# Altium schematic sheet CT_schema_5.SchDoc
size 368 x 245 mm
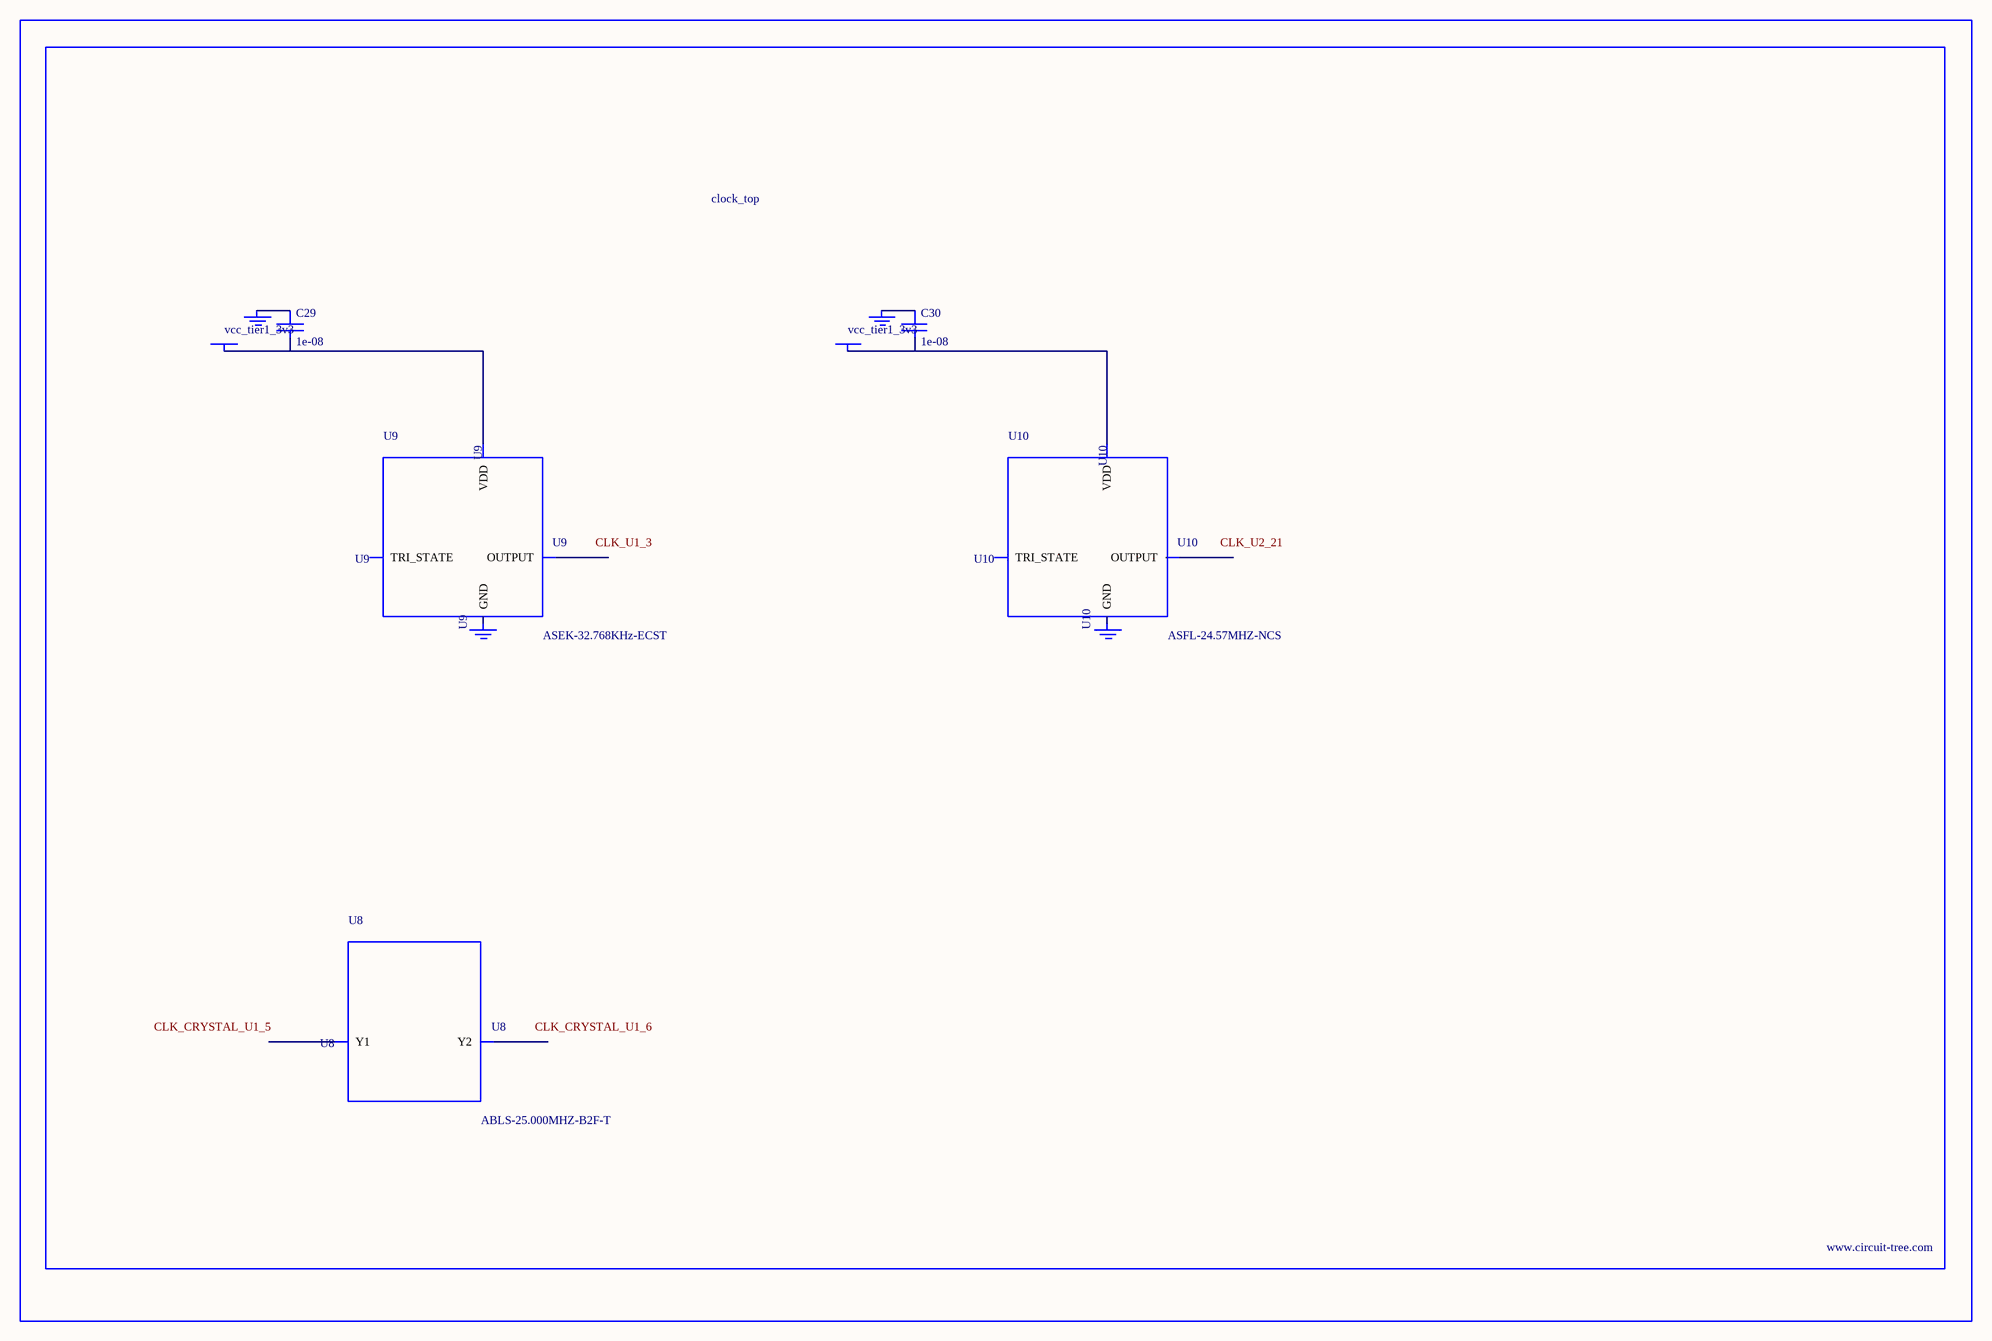
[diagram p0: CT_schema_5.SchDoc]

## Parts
BORDER4  (no value)
C29  1e-08  [C0402]
C30  1e-08  [C0402]
GND_INSTANCE_4_0  (no value)
GND_INSTANCE_4_1  (no value)
GND_INSTANCE_4_2  (no value)
GND_INSTANCE_4_3  (no value)
POWER_INSTANCE_4_0  vcc_tier1_3v3
POWER_INSTANCE_4_1  vcc_tier1_3v3
U8  ABLS-25.000MHZ-B2F-T  [ABLS-25.000MHZ-B2F-T]
U9  ASEK-32.768KHz-ECST  [ASEK]
U10  ASFL-24.57MHZ-NCS  [ASFL1]

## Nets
NetC29_1: C29.1 GND_INSTANCE_4_0.0(GND)
NetC29_2: C29.2 POWER_INSTANCE_4_0.0(PWR) U9.4(VDD)
NetC30_1: C30.1 GND_INSTANCE_4_2.0(GND)
NetC30_2: C30.2 POWER_INSTANCE_4_1.0(PWR) U10.4(VDD)

Not connected (* = marked no-connect by the designer): GND_INSTANCE_4_1 0(GND); GND_INSTANCE_4_3 0(GND); U8 1(Y1) 2(Y2); U9 1(TRI_STATE) 2(GND) 3(OUTPUT); U10 1(TRI_STATE) 2(GND) 3(OUTPUT)

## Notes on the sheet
- Labels drawn without touching a wire or pin: CLK_CRYSTAL_U1_5, CLK_CRYSTAL_U1_6, CLK_U1_3, CLK_U2_21

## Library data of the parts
BORDER4 = BORDER_PAGE4
C29 C30 = C0402C103K3RAC
GND_INSTANCE_4_0-GND_INSTANCE_4_3 = GND
POWER_INSTANCE_4_0 POWER_INSTANCE_4_1 = PWR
